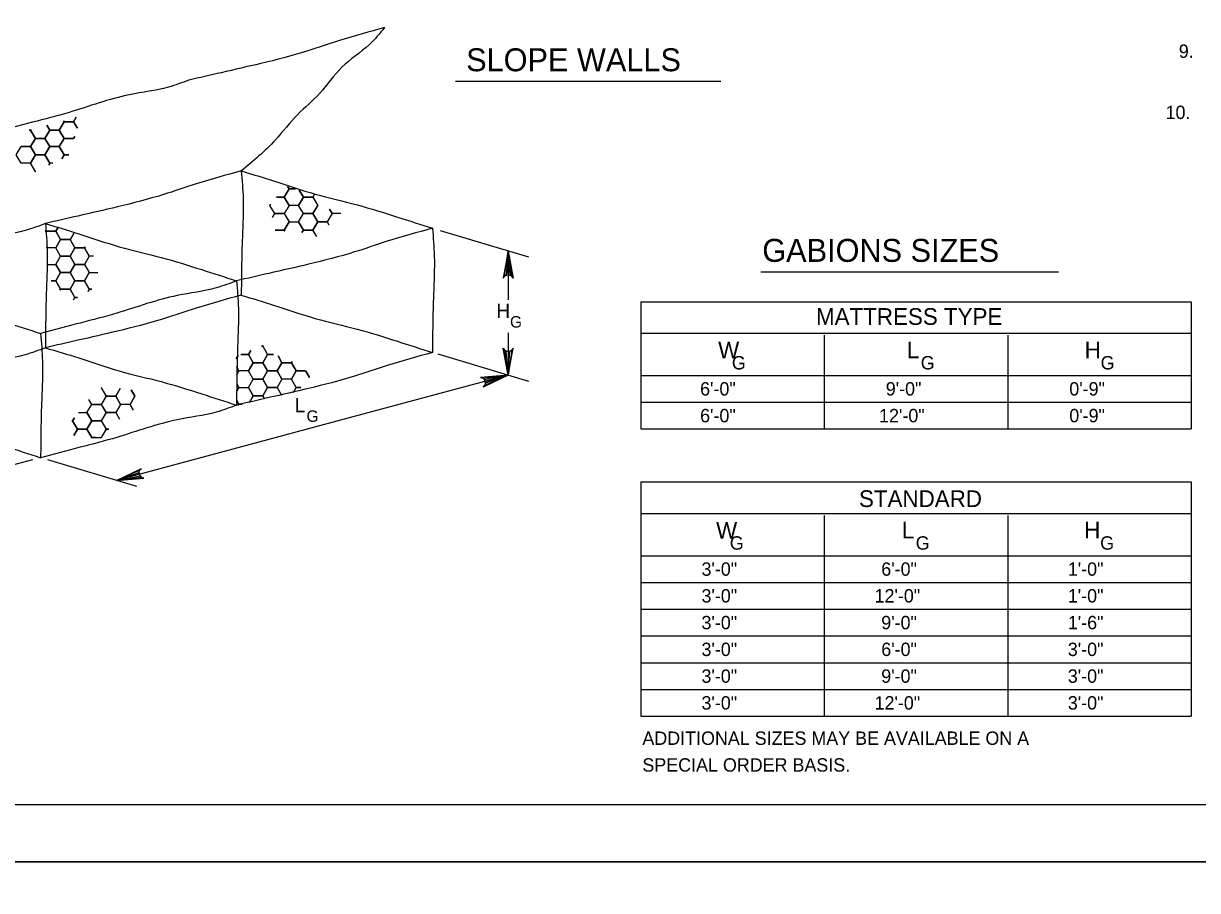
# Model space of a CAD drawing. Extents: x 3 to 3592, y -602 to 1171.
# Drawn here: x 298.8 to 605.9, y 569.3 to 796.1 of the extents above; entities that cross this region are included whole.
import ezdxf

# ---------------------------------------------------------------- set-up
doc = ezdxf.new("R2010")
doc.units = 0
for name, color, linetype in [('1', 7, 'Continuous'), ('2', 7, 'Continuous'), ('3', 7, 'Continuous'), ('PLT-BNDY', 7, 'Continuous')]:
    doc.layers.add(name, color=color, linetype=linetype)

msp = doc.modelspace()

# ---------------------------------------------------------------- linework, layer by layer
at = {"layer": '1'}
msp.add_lwpolyline([(827.51, 591.83), (827.51, 1155.83), (41.51, 1155.83), (41.51, 591.83), (827.51, 591.83), (827.51, 618.19), (627.51, 618.19), (627.51, 682.87), (827.51, 682.87), (827.51, 711.83), (627.51, 711.83), (627.51, 591.83), (706.31, 591.83), (706.31, 618.19), (706.31, 591.83), (783.31, 591.83), (783.31, 618.19), (783.31, 605.88), (827.51, 605.88)], dxfattribs=at)
at = {"layer": '2'}
for p, q in [((431, 734.99), (407.9, 741.92)), ((425.6, 736.61), (425.6, 723.86)), ((355.84, 729.27), (355.79, 725.05)), ((304.59, 715.44), (304.54, 711.3)), ((425.6, 715.23), (425.6, 704.11)), ((431, 702.49), (407.3, 709.6)), ((425.6, 704.11), (384.03, 692.96)), ((384.03, 692.96), (323.1, 676.61)), ((301.16, 681.98), (273.31, 674.51)), ((328.5, 674.99), (305.22, 681.97)), ((557.59, 614.92), (557.59, 614.92))]:
    msp.add_line(p, q, dxfattribs=at)
for points in [[(312.63, 771.62), (311.93, 770.41)], [(311.93, 770.41), (312.63, 771.62)], [(300.68, 768.24), (300.26, 768.24)], [(300.26, 768.24), (300.68, 768.24)], [(300.76, 768.38), (300.68, 768.24)], [(300.68, 768.24), (300.76, 768.38)], [(301.93, 766.08), (300.68, 768.24)], [(300.68, 768.24), (301.93, 766.08)], [(305.68, 768.24), (304.43, 766.08)], [(305.68, 768.24), (304.94, 769.52)], [(304.94, 769.52), (305.68, 768.24)], [(308.18, 768.24), (305.68, 768.24)], [(309.43, 770.41), (308.18, 768.24)], [(308.18, 768.24), (309.43, 770.41)], [(309.43, 766.08), (308.18, 768.24)], [(309.26, 770.7), (309.43, 770.41)], [(309.43, 770.41), (309.26, 770.7)], [(309.43, 770.41), (311.93, 770.41)], [(311.93, 770.41), (309.43, 770.41)], [(311.93, 770.41), (312.9, 768.73)], [(312.9, 768.73), (311.93, 770.41)], [(301.93, 766.08), (300.68, 763.91)], [(304.43, 766.08), (301.93, 766.08)], [(308.18, 763.91), (309.43, 766.08)], [(311.93, 766.08), (309.43, 766.08)], [(309.43, 766.08), (311.93, 766.08)], [(312.22, 766.58), (311.93, 766.08)], [(311.93, 766.08), (312.22, 766.58)], [(312.01, 765.93), (311.93, 766.08)], [(311.93, 766.08), (312.01, 765.93)], [(300.68, 763.91), (298.18, 763.91)], [(300.68, 759.58), (301.93, 761.75)], [(301.93, 761.75), (304.43, 761.75)], [(304.43, 761.75), (305.68, 763.91)], [(305.68, 759.58), (304.43, 761.75)], [(304.43, 761.75), (305.68, 759.58)], [(305.68, 763.91), (308.18, 763.91)], [(309.43, 761.75), (308.18, 763.91)], [(308.18, 763.91), (309.43, 761.75)], [(309.43, 761.75), (308.84, 760.72)], [(308.84, 760.72), (309.43, 761.75)], [(310.69, 761.75), (309.43, 761.75)], [(309.43, 761.75), (310.69, 761.75)], [(301.93, 757.42), (300.68, 759.58)], [(305.68, 759.58), (305.36, 759.04)], [(306.48, 759.58), (305.68, 759.58)], [(301.89, 757.35), (301.93, 757.42)], [(301.93, 757.42), (302.02, 757.42)], [(302.02, 757.42), (301.93, 757.42)], [(368.27, 752.87), (367.02, 750.71)], [(367.02, 750.71), (368.27, 752.87)], [(367.91, 753.5), (368.27, 752.87)], [(368.27, 752.87), (367.91, 753.5)], [(368.27, 752.87), (369.93, 752.87)], [(369.93, 752.87), (368.27, 752.87)], [(370.96, 752.55), (372.02, 750.71)], [(372.02, 750.71), (370.96, 752.55)], [(367.02, 750.71), (364.98, 750.71)], [(364.98, 750.71), (367.02, 750.71)], [(368.27, 748.54), (367.02, 750.71)], [(367.02, 750.71), (368.27, 748.54)], [(372.02, 750.71), (370.77, 748.54)], [(374.52, 750.71), (372.02, 750.71)], [(374.89, 751.33), (374.52, 750.71)], [(363.27, 748.54), (363.22, 748.54)], [(363.44, 748.83), (363.27, 748.54)], [(363.27, 748.54), (363.44, 748.83)], [(364.52, 746.38), (363.27, 748.54)], [(363.93, 745.35), (364.52, 746.38)], [(364.52, 746.38), (367.02, 746.38)], [(367.02, 746.38), (364.52, 746.38)], [(368.27, 748.54), (367.02, 746.38)], [(367.02, 746.38), (368.27, 744.21)], [(370.77, 748.54), (368.27, 748.54)], [(374.54, 746.38), (375.77, 748.51)], [(375.79, 744.22), (374.54, 746.38)], [(379.54, 746.38), (378.29, 744.22)], [(379.54, 746.38), (378.86, 747.56)], [(378.86, 747.56), (379.54, 746.38)], [(381.79, 746.38), (379.54, 746.38)], [(368.27, 744.21), (367.02, 742.05)], [(367.02, 742.05), (368.27, 744.21)], [(368.27, 744.21), (370.77, 744.21)], [(370.77, 744.21), (372.02, 742.05)], [(374.54, 742.05), (375.79, 744.22)], [(375.79, 744.22), (378.29, 744.22)], [(378.29, 744.22), (375.79, 744.22)], [(378.29, 744.22), (378.73, 743.46)], [(304.6, 742.07), (304.77, 741.77)], [(304.77, 741.77), (304.6, 742.07)], [(304.77, 741.77), (304.61, 741.51)], [(304.61, 741.51), (304.77, 741.77)], [(304.77, 741.77), (307.27, 741.77)], [(307.27, 741.77), (304.77, 741.77)], [(307.8, 742.7), (307.27, 741.77)], [(307.27, 741.77), (307.8, 742.7)], [(307.27, 741.77), (308.52, 739.61)], [(308.52, 739.61), (307.27, 741.77)], [(311.98, 741.28), (311.02, 739.61)], [(364.67, 742.05), (367.02, 742.05)], [(367.02, 742.05), (364.67, 742.05)], [(367.02, 742.05), (367.17, 741.79)], [(367.17, 741.79), (367.02, 742.05)], [(372.02, 742.05), (371.65, 741.41)], [(371.65, 741.41), (372.02, 742.05)], [(372.02, 742.05), (374.52, 742.05)], [(374.52, 742.05), (375.06, 741.11)], [(375.51, 740.38), (374.54, 742.05)], [(304.77, 737.44), (304.75, 737.46)], [(304.75, 737.46), (304.77, 737.44)], [(304.77, 737.44), (304.76, 737.42)], [(307.27, 737.44), (304.77, 737.44)], [(308.52, 739.61), (307.27, 737.44)], [(311.02, 739.61), (308.52, 739.61)], [(311.02, 735.28), (312.27, 737.44)], [(312.27, 737.44), (311.44, 738.88)], [(314.77, 737.44), (312.27, 737.44)], [(312.27, 737.44), (314.77, 737.44)], [(314.92, 737.7), (314.77, 737.44)], [(314.77, 737.44), (314.92, 737.7)], [(316.02, 735.28), (314.77, 737.44)], [(314.77, 737.44), (316.02, 735.28)], [(312.27, 733.11), (311.02, 735.28)], [(316.02, 735.28), (314.77, 733.11)], [(317.14, 735.28), (316.02, 735.28)], [(425.6, 736.61), (426.93, 729.48), (426.55, 730.03), (425.6, 736.61), (426.07, 730.31), (425.6, 730.39), (425.6, 736.61), (425.12, 730.31), (424.64, 730.03), (425.6, 736.61), (424.26, 729.48), (424.64, 730.03), (425.12, 730.31), (425.6, 730.39), (426.07, 730.31), (426.55, 730.03)], [(304.91, 733.11), (307.27, 733.11)], [(307.27, 733.11), (308.52, 730.95)], [(314.77, 733.11), (312.27, 733.11)], [(306.01, 728.78), (307.27, 728.78)], [(307.27, 728.78), (306.01, 728.78)], [(308.52, 730.95), (307.27, 728.78)], [(307.27, 728.78), (308.52, 730.95)], [(307.27, 728.78), (308.52, 726.62)], [(308.52, 726.62), (307.27, 728.78)], [(308.52, 730.95), (311.02, 730.95)], [(311.02, 730.95), (312.27, 728.78)], [(312.27, 728.78), (311.02, 726.62)], [(311.02, 726.62), (312.27, 728.78)], [(312.27, 728.78), (314.77, 728.78)], [(314.77, 728.78), (316.02, 730.95)], [(316.02, 726.62), (314.77, 728.78)], [(314.77, 728.78), (316.02, 726.62)], [(316.02, 730.95), (318.27, 730.95)], [(308.52, 726.62), (308.35, 726.33)], [(308.35, 726.33), (308.52, 726.62)], [(308.52, 726.62), (311.02, 726.62)], [(311.02, 726.62), (308.52, 726.62)], [(311.02, 726.62), (311.83, 725.21)], [(312.27, 724.45), (311.02, 726.62)], [(316.02, 726.62), (315.7, 726.06)], [(315.7, 726.06), (316.02, 726.62)], [(316.65, 726.62), (316.02, 726.62)], [(316.02, 726.62), (316.65, 726.62)], [(311.91, 723.83), (312.27, 724.45)], [(312.97, 724.45), (312.27, 724.45)], [(312.27, 724.45), (312.97, 724.45)], [(355.7, 709.56), (357.67, 709.56)], [(357.67, 709.56), (355.7, 709.56)], [(358.27, 710.6), (357.67, 709.56)], [(357.67, 709.56), (358.27, 710.6)], [(357.67, 709.56), (358.92, 707.4)], [(358.92, 707.4), (357.67, 709.56)], [(361.05, 711.73), (361.42, 711.73)], [(361.42, 711.73), (361.05, 711.73)], [(361.53, 711.92), (361.42, 711.73)], [(361.42, 711.73), (362.67, 709.56)], [(362.67, 709.56), (361.42, 707.4)], [(361.42, 707.4), (362.67, 709.56)], [(362.67, 709.56), (362.31, 710.19)], [(364.19, 709.56), (362.67, 709.56)], [(362.67, 709.56), (364.19, 709.56)], [(425.6, 704.11), (424.26, 711.24), (424.64, 710.69), (425.6, 704.11), (425.12, 710.41), (425.6, 710.33), (425.6, 704.11), (426.07, 710.41), (426.55, 710.69), (425.6, 704.11), (426.93, 711.24), (426.55, 710.69), (426.07, 710.41), (425.6, 710.33), (425.12, 710.41), (424.64, 710.69)], [(355.01, 709.29), (354.49, 708.39)], [(354.49, 708.39), (355.01, 709.29)], [(358.92, 707.4), (357.67, 705.23)], [(361.42, 707.4), (358.92, 707.4)], [(362.67, 705.23), (361.42, 707.4)], [(366.42, 707.4), (365.17, 705.23)], [(365.17, 705.23), (366.42, 707.4)], [(366.42, 707.4), (365.4, 709.16)], [(365.4, 709.16), (366.42, 707.4)], [(368.92, 707.4), (366.42, 707.4)], [(366.42, 707.4), (368.92, 707.4)], [(369.08, 707.67), (368.92, 707.4)], [(368.92, 707.4), (369.08, 707.67)], [(370.17, 705.23), (368.92, 707.4)], [(368.92, 707.4), (370.17, 705.23)], [(355.17, 705.23), (354.52, 706.36)], [(354.52, 706.36), (355.17, 705.23)], [(355.17, 705.23), (354.55, 704.16)], [(357.67, 705.23), (355.17, 705.23)], [(365.17, 705.23), (362.67, 705.23)], [(366.42, 703.07), (365.17, 705.23)], [(370.17, 705.23), (368.92, 703.07)], [(368.92, 703.07), (370.17, 705.23)], [(372.62, 705.23), (370.17, 705.23)], [(370.17, 705.23), (372.62, 705.23)], [(373.63, 703.56), (372.7, 705.18)], [(372.7, 705.18), (373.63, 703.56)], [(425.6, 704.11), (419.05, 700.97), (419.49, 701.48), (425.6, 704.11), (419.64, 702.02), (419.59, 702.5), (425.6, 704.11), (419.39, 702.94), (418.99, 703.33), (425.6, 704.11), (418.36, 703.55), (418.99, 703.33), (419.39, 702.94), (419.59, 702.5), (419.64, 702.02), (419.49, 701.48)], [(319.13, 700.83), (319.17, 700.83)], [(319.17, 700.83), (319.13, 700.83)], [(319.2, 700.88), (319.17, 700.83)], [(319.17, 700.83), (320.42, 698.66)], [(324.08, 700.66), (322.93, 698.66)], [(322.93, 698.66), (324.08, 700.66)], [(327.93, 698.66), (326.99, 700.29)], [(326.99, 700.29), (327.93, 698.66)], [(354.58, 701.92), (355.17, 700.9)], [(355.17, 700.9), (354.61, 699.93)], [(354.61, 699.93), (355.17, 700.9)], [(355.17, 700.9), (357.67, 700.9)], [(357.67, 700.9), (358.92, 698.74)], [(361.42, 698.74), (362.67, 700.9)], [(362.67, 700.9), (365.17, 700.9)], [(365.17, 700.9), (366.32, 698.92)], [(368.92, 703.07), (366.42, 703.07)], [(370.17, 700.9), (368.92, 703.07)], [(369.43, 699.63), (370.17, 700.9)], [(370.17, 700.9), (371.37, 700.9)], [(371.37, 700.9), (370.17, 700.9)], [(316.67, 696.5), (315.94, 697.76)], [(320.42, 698.66), (319.17, 696.5)], [(320.43, 698.66), (319.62, 700.08)], [(322.93, 698.66), (320.43, 698.66)], [(324.18, 696.5), (322.93, 698.66)], [(327.93, 698.66), (326.68, 696.5)], [(326.68, 696.5), (327.93, 698.66)], [(328.04, 698.66), (327.93, 698.66)], [(327.93, 698.66), (328.04, 698.66)], [(354.65, 697.48), (355.17, 696.57)], [(355.17, 696.57), (354.65, 697.48)], [(358.92, 698.74), (357.92, 697)], [(357.92, 697), (358.92, 698.74)], [(358.92, 698.74), (361.42, 698.74)], [(361.42, 698.74), (361.9, 697.91)], [(361.9, 697.91), (361.42, 698.74)], [(313.21, 694.33), (315.42, 694.33)], [(315.42, 694.33), (316.67, 692.17)], [(319.17, 696.5), (316.67, 696.5)], [(319.18, 692.17), (320.43, 694.33)], [(320.43, 694.33), (322.93, 694.33)], [(322.93, 694.33), (323.92, 692.62)], [(326.68, 696.5), (324.18, 696.5)], [(327.55, 695), (326.68, 696.5)], [(354.99, 696.26), (354.97, 696.22)], [(354.97, 696.22), (354.99, 696.26)], [(355.17, 696.57), (355.04, 696.34)], [(355.04, 696.34), (355.17, 696.57)], [(355.17, 696.57), (356.04, 696.57)], [(356.04, 696.57), (355.17, 696.57)], [(311.49, 692.17), (311.67, 692.17)], [(311.67, 692.17), (311.49, 692.17)], [(312.14, 692.98), (311.67, 692.17)], [(311.67, 692.17), (312.14, 692.98)], [(311.67, 692.17), (312.92, 690)], [(312.92, 690), (311.67, 692.17)], [(316.67, 692.17), (315.42, 690)], [(315.42, 690), (316.67, 692.17)], [(316.67, 692.17), (319.17, 692.17)], [(319.17, 692.17), (320.42, 690)], [(320.43, 690), (319.18, 692.17)], [(312.92, 690), (311.95, 688.32)], [(311.95, 688.32), (312.92, 690)], [(312.92, 690), (315.42, 690)], [(315.42, 690), (312.92, 690)], [(315.42, 690), (316.67, 687.84)], [(316.67, 687.84), (315.42, 690)], [(320.42, 690), (319.17, 687.84)], [(319.18, 687.84), (320.43, 690)], [(320.6, 689.69), (320.42, 690)], [(321.1, 690), (320.43, 690)], [(320.43, 690), (321.1, 690)], [(316.67, 687.84), (316.57, 687.66)], [(316.57, 687.66), (316.67, 687.84)], [(316.67, 687.84), (319.17, 687.84)], [(317.68, 687.84), (316.67, 687.84)], [(323.1, 676.61), (329.64, 679.75), (329.2, 679.24), (323.1, 676.61), (329.05, 678.7), (329.1, 678.22), (323.1, 676.61), (329.3, 677.78), (329.7, 677.39), (323.1, 676.61), (330.33, 677.17), (329.7, 677.39), (329.3, 677.78), (329.1, 678.22), (329.05, 678.7), (329.2, 679.24)]]:
    msp.add_lwpolyline(points, dxfattribs=at)
for points in [[(304.43, 766.08), (305.68, 768.24), (308.18, 768.24), (309.43, 766.08), (308.18, 763.91), (305.68, 763.91)], [(300.68, 763.91), (301.93, 766.08), (304.43, 766.08), (305.68, 763.91), (304.43, 761.75), (301.93, 761.75)], [(296.93, 761.75), (298.18, 763.91), (300.68, 763.91), (301.93, 761.75), (300.68, 759.58), (298.18, 759.58)], [(370.77, 748.54), (372.02, 750.71), (374.52, 750.71), (375.77, 748.54), (374.52, 746.38), (372.02, 746.38)], [(370.77, 744.21), (372.02, 746.38), (374.52, 746.38), (375.77, 744.21), (374.52, 742.05), (372.02, 742.05)], [(307.27, 737.44), (308.52, 739.61), (311.02, 739.61), (312.27, 737.44), (311.02, 735.28), (308.52, 735.28)], [(307.27, 733.11), (308.52, 735.28), (311.02, 735.28), (312.27, 733.11), (311.02, 730.95), (308.52, 730.95)], [(311.02, 730.95), (312.27, 733.11), (314.77, 733.11), (316.02, 730.95), (314.77, 728.78), (312.27, 728.78)], [(357.67, 705.23), (358.92, 707.4), (361.42, 707.4), (362.67, 705.23), (361.42, 703.07), (358.92, 703.07)], [(361.42, 703.07), (362.67, 705.23), (365.17, 705.23), (366.42, 703.07), (365.17, 700.9), (362.67, 700.9)], [(357.67, 700.9), (358.92, 703.07), (361.42, 703.07), (362.67, 700.9), (361.42, 698.74), (358.92, 698.74)], [(319.18, 696.5), (320.43, 698.66), (322.93, 698.66), (324.18, 696.5), (322.93, 694.33), (320.43, 694.33)], [(315.42, 694.33), (316.67, 696.5), (319.17, 696.5), (320.42, 694.33), (319.17, 692.17), (316.67, 692.17)]]:
    msp.add_lwpolyline(points, close=True, dxfattribs=at)
for points in [[(393.29, 795.05), (381.49, 791.66), (372.9, 788.86), (360.91, 785.66), (350.52, 783.26), (342.04, 781.3)], [(393.29, 795.05), (389.29, 790.66), (382.09, 784.66), (376.3, 777.87), (370.5, 772.27), (364.71, 765.68), (355.79, 757.55)], [(342.04, 781.3), (336.73, 779.47), (326.54, 777.47), (310.75, 772.87), (301.16, 770.27), (290.79, 767.55)], [(355.79, 757.55), (343.99, 754.16), (335.4, 751.36), (323.41, 748.16), (313.02, 745.76), (304.54, 743.8)], [(355.79, 757.55), (364.51, 754.89), (375.1, 751.49), (386.09, 748.69), (396.68, 745.49), (405.79, 742.55)], [(355.79, 757.55), (356.27, 750.3), (356.07, 740.31), (355.87, 732.32), (355.84, 729.27)], [(304.54, 743.8), (299.23, 741.97), (289.04, 739.97), (273.25, 735.37), (263.66, 732.77), (253.29, 730.05)], [(304.54, 743.8), (313.26, 741.14), (323.85, 737.74), (334.84, 734.94), (345.43, 731.74), (354.54, 728.8)], [(304.54, 743.8), (305.02, 736.55), (304.82, 726.56), (304.62, 718.57), (304.59, 715.44)], [(405.79, 742.55), (393.99, 739.16), (385.4, 736.36), (373.41, 733.16), (363.02, 730.76), (354.54, 728.8)], [(405.79, 742.55), (406.27, 735.3), (406.07, 725.31), (405.87, 717.32), (405.79, 710.05)], [(253.29, 730.05), (262.01, 727.39), (272.6, 723.99), (283.59, 721.19), (294.18, 717.99), (303.29, 715.05)], [(354.54, 728.8), (349.23, 726.97), (339.04, 724.97), (323.25, 720.37), (313.66, 717.77), (303.29, 715.05)], [(354.54, 728.8), (355.02, 721.55), (354.82, 711.56), (354.62, 703.57), (354.54, 696.3)], [(355.79, 725.05), (343.99, 721.66), (335.4, 718.86), (323.41, 715.66), (313.02, 713.26), (304.54, 711.3)], [(355.79, 725.05), (364.51, 722.39), (375.1, 718.99), (386.09, 716.19), (396.68, 712.99), (405.79, 710.05)], [(303.29, 715.05), (303.77, 707.8), (303.57, 697.81), (303.37, 689.82), (303.29, 682.55)], [(304.54, 711.3), (299.23, 709.47), (289.04, 707.47), (273.25, 702.87), (263.66, 700.27), (253.29, 697.55)], [(304.54, 711.3), (313.26, 708.64), (323.85, 705.24), (334.84, 702.44), (345.43, 699.24), (354.54, 696.3)], [(405.79, 710.05), (393.99, 706.66), (385.4, 703.86), (373.41, 700.66), (363.02, 698.26), (354.54, 696.3)], [(253.29, 697.55), (262.01, 694.89), (272.6, 691.49), (283.59, 688.69), (294.18, 685.49), (303.29, 682.55)], [(354.54, 696.3), (349.23, 694.47), (339.04, 692.47), (323.25, 687.87), (313.66, 685.27), (303.29, 682.55)]]:
    msp.add_spline(points, degree=3, dxfattribs=at)
at = {"layer": '3'}
for p, q in [((411.86, 781.01), (481.21, 781.01)), ((491.67, 731.2), (569.58, 731.2)), ((460.29, 723.34), (604.3, 723.34)), ((460.29, 723.34), (460.29, 690.06)), ((604.3, 723.34), (604.3, 690.06)), ((460.29, 715.09), (604.3, 715.09)), ((508.29, 714.59), (508.29, 690.06)), ((556.3, 714.59), (556.3, 690.06)), ((460.29, 704.06), (604.3, 704.06)), ((460.29, 697.06), (604.3, 697.06)), ((460.29, 690.06), (604.3, 690.06)), ((516.8, 690.06), (542.66, 690.06)), ((545.18, 690.06), (568.62, 690.06)), ((460.29, 676.2), (604.29, 676.2)), ((460.29, 676.2), (460.29, 614.92)), ((604.29, 676.2), (604.29, 614.92)), ((460.29, 667.95), (604.29, 667.95)), ((508.29, 667.45), (508.29, 614.92)), ((556.29, 667.45), (556.29, 614.92)), ((460.29, 656.92), (604.29, 656.92)), ((460.29, 649.92), (604.29, 649.92)), ((460.29, 642.92), (604.29, 642.92)), ((508.29, 642.92), (534.15, 642.92)), ((534.15, 642.92), (557.59, 642.92)), ((460.29, 635.92), (604.29, 635.92)), ((460.29, 628.92), (604.29, 628.92)), ((460.29, 621.92), (604.29, 621.92)), ((460.29, 614.92), (604.29, 614.92))]:
    msp.add_line(p, q, dxfattribs=at)
at = {"layer": 'PLT-BNDY'}
for points in [[(2.51, 1170.83), (843.51, 1170.83), (843.51, 576.83), (2.51, 576.83)], [(2.51, 576.83), (843.51, 576.83), (843.51, -17.17), (2.51, -17.17)]]:
    msp.add_lwpolyline(points, close=True, dxfattribs=at)

# ---------------------------------------------------------------- texts
at = {"layer": '3'}
for s, height, p in [('SLOPE WALLS', 6, (414.61, 783.63)), ('9.  ', 3.5, (601.04, 787.13)), ('10.  ', 3.5, (597.57, 771.13)), ('GABIONS SIZES', 6, (492.08, 733.77)), ('H', 3.75, (422.5, 719.1)), ('G', 3, (426.09, 716.59)), ('MATTRESS TYPE', 4.375, (506.13, 717.29)), ('W', 4.38, (480.53, 708.5)), ('L', 4.38, (529.9, 708.56)), ('H', 4.38, (576.39, 708.56)), ('G', 3.5, (484.12, 705.63)), ('G', 3.5, (533.53, 705.63)), ('G', 3.5, (580.58, 705.63)), ('6\'-0"', 3.5, (475.81, 698.81)), ('9\'-0"', 3.5, (524.38, 698.81)), ('0\'-9"', 3.5, (572.39, 698.81)), ('L', 3.75, (369.77, 694.43)), ('G', 3, (372.87, 691.92)), ('6\'-0"', 3.5, (475.81, 691.81)), ('12\'-0"', 3.5, (522.63, 691.81)), ('0\'-9"', 3.5, (572.39, 691.81)), ('STANDARD', 4.375, (517.37, 669.64)), ('W', 4.38, (479.99, 661.36)), ('L', 4.38, (528.59, 661.42)), ('H', 4.38, (576.28, 661.42)), ('G', 3.5, (483.58, 658.49)), ('G', 3.5, (532.22, 658.49)), ('G', 3.5, (580.47, 658.49)), ('3\'-0"', 3.5, (476.17, 651.67)), ('6\'-0"', 3.5, (523.2, 651.67)), ('1\'-0"', 3.5, (572, 651.67)), ('3\'-0"', 3.5, (476.17, 644.67)), ('12\'-0"', 3.5, (521.45, 644.67)), ('1\'-0"', 3.5, (572, 644.67)), ('3\'-0"', 3.5, (476.17, 637.67)), ('9\'-0"', 3.5, (523.2, 637.67)), ('1\'-6"', 3.5, (572, 637.67)), ('3\'-0"', 3.5, (476.17, 630.67)), ('6\'-0"', 3.5, (523.2, 630.67)), ('3\'-0"', 3.5, (572, 630.67)), ('3\'-0"', 3.5, (476.17, 623.67)), ('9\'-0"', 3.5, (523.2, 623.67)), ('3\'-0"', 3.5, (572, 623.67)), ('3\'-0"', 3.5, (476.17, 616.67)), ('12\'-0"', 3.5, (521.45, 616.67)), ('3\'-0"', 3.5, (572, 616.67)), ('ADDITIONAL SIZES MAY BE AVAILABLE ON A', 3.5, (460.71, 607.43)), ('SPECIAL ORDER BASIS. ', 3.5, (460.71, 600.43))]:
    msp.add_text(s, height=height, dxfattribs=at).set_placement(p)

doc.saveas('drawing.dxf')
